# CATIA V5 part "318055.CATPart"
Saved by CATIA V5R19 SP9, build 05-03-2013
Part number: 318055
Source: Unknown
Bounding box of the stored display mesh (mm): x -692.228 to 122.767, y -247.287 to -88.111, z 189.403 to 590.351
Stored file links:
  D:\16-SIL\kale oto\R19_V1\318055.CATPart
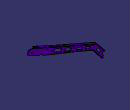
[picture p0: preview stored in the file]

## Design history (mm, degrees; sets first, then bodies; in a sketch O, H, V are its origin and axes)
Body1 "157\\125\\MANIFOLD_SOLID_BREP #78028" (main body)
  Solid1: solid without history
